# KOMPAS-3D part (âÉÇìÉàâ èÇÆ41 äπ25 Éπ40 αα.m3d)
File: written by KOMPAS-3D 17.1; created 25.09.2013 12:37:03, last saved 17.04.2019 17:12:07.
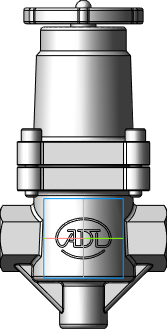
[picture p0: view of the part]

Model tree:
1. Операция без истории:3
